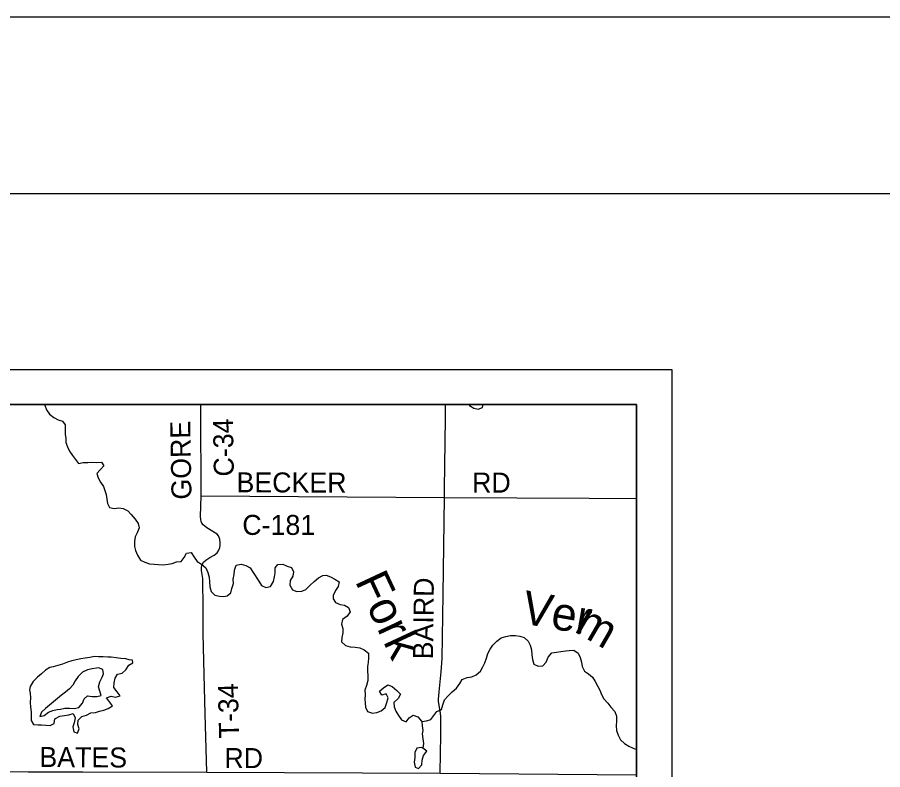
# Model space of a CAD drawing. Extents: x 0 to 34, y 0 to 22.
# Drawn here: x 7.141 to 9.599, y 19.863 to 22 of the extents above; entities that cross this region are included whole.
import ezdxf

# ---------------------------------------------------------------- set-up
doc = ezdxf.new("R2010")
doc.units = 0
for name, color, linetype in [('GM_X_Corporation', 7, 'Continuous'), ('GM_X_County_Road', 7, 'Continuous'), ('GM_X_County_Road_Text', 7, 'Continuous'), ('GM_X_Minor_Lake', 7, 'Continuous'), ('GM_X_Minor_River', 7, 'Continuous'), ('GM_X_Minor_River_Text', 7, 'Continuous'), ('GM_X_Township_Road', 7, 'Continuous'), ('GM_X_Township_Road_Text', 7, 'Continuous'), ('SH_Border', 7, 'Continuous'), ('SH_Cut_Line', 7, 'Continuous'), ('SH_Data', 7, 'Continuous')]:
    doc.layers.add(name, color=color, linetype=linetype)

msp = doc.modelspace()

# ---------------------------------------------------------------- linework, layer by layer
at = {"layer": 'GM_X_Corporation'}
msp.add_lwpolyline([(8.9, 14.1), (8.9, 20.9), (6.9799, 20.9), (6.9799, 20.8943), (6.9814, 20.8368), (6.9837, 20.7502), (6.9864, 20.657), (6.9927, 20.4427), (6.9931, 20.4255), (6.9989, 19.9212), (7.0018, 19.871), (7.0046, 19.8599), (7.0077, 19.6756), (7.0107, 19.4664), (7.0305, 18.5559), (7.0429, 18.0629), (7.0494, 17.8247), (7.0577, 17.449), (7.0649, 17.2134), (7.0651, 17.204), (7.0717, 16.9849), (7.0838, 16.6084), (7.1072, 15.3824)], dxfattribs=at)
msp.add_lwpolyline([(8.9, 19.8484), (8.9, 20.9), (6.9799, 20.9), (6.9799, 20.8943), (6.9814, 20.8368), (6.9837, 20.7502), (6.9864, 20.657), (6.9927, 20.4427), (6.9931, 20.4255), (6.9989, 19.9212), (7.0018, 19.871), (7.0046, 19.8599), (7.1717, 19.8568), (7.3272, 19.8568), (7.6795, 19.8561), (8.3424, 19.8533)], close=True, dxfattribs=at)
at = {"layer": 'GM_X_County_Road'}
for points in [[(7.663, 20.6406), (7.6626, 20.8828), (7.6622, 20.9)], [(7.663, 20.6406), (8.3545, 20.636), (8.7653, 20.634), (8.9, 20.6328)]]:
    msp.add_lwpolyline(points, dxfattribs=at)
at = {"layer": 'GM_X_Minor_Lake'}
for points in [[(7.4688, 20.1739), (7.459, 20.1752), (7.4491, 20.1774), (7.4354, 20.1792), (7.4217, 20.1805), (7.408, 20.1823), (7.3985, 20.1825), (7.3855, 20.1835), (7.3722, 20.1837), (7.3604, 20.184), (7.3475, 20.1819), (7.3342, 20.1799), (7.3213, 20.1778), (7.3084, 20.175), (7.2963, 20.1722), (7.2834, 20.1679), (7.2694, 20.1628), (7.2568, 20.1592), (7.2436, 20.1553), (7.2341, 20.1533), (7.2216, 20.1459), (7.2096, 20.1351), (7.1983, 20.1255), (7.1859, 20.1132), (7.178, 20.0994), (7.1755, 20.0895), (7.1775, 20.08), (7.1784, 20.0671), (7.1782, 20.0538), (7.1791, 20.0409), (7.1804, 20.0276), (7.1809, 20.0155), (7.1806, 20.0025), (7.1872, 19.9912)], [(7.1872, 19.9912), (7.2002, 19.9906), (7.2097, 19.9903), (7.2226, 19.9893), (7.2344, 19.9887), (7.2462, 19.9942), (7.2483, 20.0071), (7.2619, 20.0153), (7.2756, 20.0166), (7.2881, 20.019), (7.3002, 20.0225), (7.3061, 20.0101), (7.3028, 19.9964), (7.2988, 19.9845), (7.3016, 19.9709), (7.3127, 19.9664), (7.3167, 19.979), (7.3131, 19.9911), (7.3145, 20.0037), (7.3247, 20.0137), (7.3379, 20.018), (7.35, 20.0246), (7.3637, 20.0256), (7.3751, 20.0287), (7.3872, 20.0319), (7.3997, 20.037), (7.4114, 20.044), (7.4033, 20.0557), (7.3944, 20.067), (7.4077, 20.072), (7.4203, 20.0692), (7.4332, 20.0727), (7.4251, 20.0844), (7.4154, 20.0965), (7.4168, 20.1094), (7.4193, 20.1231), (7.4256, 20.1346), (7.4389, 20.1374), (7.4498, 20.147), (7.4577, 20.16), (7.4698, 20.1666), (7.4688, 20.1739)], [(7.2548, 20.0338), (7.2636, 20.035), (7.2765, 20.0375), (7.2894, 20.038), (7.3031, 20.0363), (7.3156, 20.0394), (7.3261, 20.0521), (7.331, 20.0639), (7.3407, 20.0728), (7.3537, 20.0707), (7.3674, 20.0708), (7.3799, 20.0736), (7.3756, 20.0861), (7.372, 20.0986), (7.3761, 20.1123), (7.3827, 20.1261), (7.3857, 20.1356), (7.384, 20.1478), (7.3722, 20.1522), (7.3664, 20.1513)], [(7.2548, 20.0338), (7.2636, 20.035), (7.2765, 20.0375), (7.2894, 20.038), (7.3031, 20.0363), (7.3156, 20.0394), (7.3261, 20.0521), (7.331, 20.0639), (7.3407, 20.0728), (7.3537, 20.0707), (7.3674, 20.0708), (7.3799, 20.0736), (7.3756, 20.0861), (7.372, 20.0986), (7.3761, 20.1123), (7.3827, 20.1261), (7.3857, 20.1356), (7.384, 20.1478), (7.3722, 20.1522), (7.3663, 20.1513)], [(7.3664, 20.1513), (7.3665, 20.1514), (7.3536, 20.1493), (7.3403, 20.1465), (7.3267, 20.1395), (7.3146, 20.128), (7.3056, 20.1157), (7.2986, 20.1031), (7.2899, 20.0927), (7.2782, 20.0827), (7.2669, 20.0742), (7.2552, 20.0653), (7.2443, 20.0561), (7.2326, 20.0461), (7.2213, 20.0368), (7.21, 20.0264), (7.2052, 20.0138), (7.2178, 20.017), (7.2302, 20.0267), (7.2419, 20.0314), (7.2548, 20.0338)], [(7.3664, 20.1513), (7.3536, 20.1493), (7.3403, 20.1465), (7.3267, 20.1395), (7.3146, 20.128), (7.3056, 20.1157), (7.2986, 20.1031), (7.2899, 20.0927), (7.2782, 20.0827), (7.2669, 20.0742), (7.2552, 20.0653), (7.2443, 20.0561), (7.2326, 20.0461), (7.2213, 20.0368), (7.21, 20.0264), (7.2052, 20.0138), (7.2178, 20.017), (7.2302, 20.0267), (7.2419, 20.0314), (7.2548, 20.0338)], [(8.2934, 19.9242), (8.2896, 19.926), (8.2759, 19.9244), (8.27, 19.9118), (8.2701, 19.8977), (8.2688, 19.884), (8.2708, 19.8703), (8.2808, 19.8659)], [(8.2933, 19.9243), (8.2896, 19.926), (8.2759, 19.9244), (8.27, 19.9118), (8.2701, 19.8977), (8.2688, 19.884), (8.2708, 19.8703), (8.2808, 19.8659)], [(8.2808, 19.8659), (8.2901, 19.8763), (8.2907, 19.89), (8.2952, 19.9029), (8.3045, 19.9156), (8.2934, 19.9242)], [(8.2808, 19.8659), (8.2901, 19.8763), (8.2907, 19.89), (8.2952, 19.9029), (8.3045, 19.9156), (8.2934, 19.9242)]]:
    msp.add_lwpolyline(points, dxfattribs=at)
at = {"layer": 'GM_X_Minor_River'}
for points in [[(7.2188, 20.9), (7.2196, 20.8983), (7.2246, 20.8851), (7.2324, 20.8726), (7.2451, 20.8636), (7.2573, 20.8569), (7.2699, 20.8525), (7.2769, 20.842), (7.2772, 20.8146), (7.2792, 20.8048), (7.2793, 20.7918), (7.284, 20.7797), (7.2899, 20.7676), (7.2984, 20.7556), (7.3154, 20.7322), (7.3287, 20.735), (7.3412, 20.7359), (7.3541, 20.7361), (7.3671, 20.7358), (7.3808, 20.7364), (7.387, 20.7262), (7.3768, 20.7151), (7.3674, 20.7043), (7.3706, 20.6918), (7.378, 20.6794), (7.3865, 20.6673), (7.3901, 20.6555), (7.3936, 20.6442), (7.3957, 20.6313), (7.3973, 20.6188), (7.4032, 20.6074), (7.4161, 20.6049), (7.4298, 20.6066), (7.4424, 20.6045), (7.455, 20.5978), (7.465, 20.5876), (7.4758, 20.5741), (7.4843, 20.562), (7.4875, 20.5495), (7.4816, 20.5358), (7.476, 20.5239), (7.4739, 20.511), (7.4744, 20.4973), (7.4772, 20.4852), (7.4827, 20.4719), (7.4912, 20.4583), (7.5034, 20.4528), (7.5168, 20.4476), (7.5297, 20.4463), (7.5427, 20.446), (7.5556, 20.4447), (7.5693, 20.4463), (7.5811, 20.4484), (7.5936, 20.4531), (7.6069, 20.4547), (7.6151, 20.4659), (7.6214, 20.4777), (7.6347, 20.4798), (7.6436, 20.4662), (7.6521, 20.4541), (7.664, 20.4463), (7.6763, 20.4358), (7.6826, 20.4229), (7.6865, 20.4101), (7.6867, 20.3964), (7.688, 20.3827), (7.6915, 20.3691), (7.7027, 20.3589), (7.7156, 20.3557), (7.7274, 20.3551), (7.7369, 20.3567), (7.7475, 20.3655), (7.7504, 20.3777), (7.7548, 20.3915), (7.7543, 20.404), (7.7568, 20.417), (7.7582, 20.4299), (7.763, 20.4436), (7.7766, 20.4464)], [(8.4244, 20.9), (8.4258, 20.8978), (8.4377, 20.8896), (8.4499, 20.887), (8.4627, 20.8918), (8.4642, 20.9)], [(7.7766, 20.4464), (7.79, 20.4428), (7.8026, 20.4361), (7.8111, 20.4229), (7.8274, 20.398), (7.8351, 20.3863), (7.8474, 20.3808), (7.8599, 20.3836), (7.8692, 20.397), (7.8714, 20.4103), (7.8735, 20.4225), (7.8734, 20.4362), (7.8816, 20.4458), (7.8953, 20.4471), (7.9072, 20.4411), (7.9197, 20.4375), (7.926, 20.425), (7.9242, 20.4128), (7.916, 20.4002), (7.915, 20.3872), (7.9227, 20.374), (7.9354, 20.3689), (7.949, 20.3702), (7.9608, 20.3752), (7.9724, 20.3864), (7.9845, 20.3975), (7.9962, 20.4079), (8.0086, 20.4145), (8.0185, 20.415), (8.0311, 20.411), (8.043, 20.4043), (8.0549, 20.3965), (8.0527, 20.3835), (8.0445, 20.3716), (8.0382, 20.3579), (8.0379, 20.3484), (8.0453, 20.3374), (8.0579, 20.3319), (8.0701, 20.3305), (8.0823, 20.3234), (8.087, 20.3113), (8.0777, 20.2994), (8.0648, 20.2894), (8.0623, 20.2765), (8.0659, 20.2643), (8.066, 20.2514), (8.0627, 20.2388), (8.0621, 20.2259), (8.0737, 20.2158), (8.087, 20.2121), (8.1007, 20.2108), (8.1137, 20.2086), (8.1263, 20.2038), (8.1382, 20.1937), (8.1383, 20.1808), (8.1377, 20.1671), (8.136, 20.1557), (8.1361, 20.1435), (8.137, 20.1299), (8.1368, 20.1162), (8.1328, 20.1025), (8.1283, 20.0891), (8.1289, 20.0762), (8.1279, 20.0625), (8.1295, 20.053), (8.1304, 20.0401), (8.1355, 20.0284), (8.1496, 20.0236), (8.1625, 20.0257), (8.1747, 20.0304), (8.186, 20.04), (8.1911, 20.0537), (8.1948, 20.0667), (8.1886, 20.0788), (8.1761, 20.0748), (8.1698, 20.0858), (8.1811, 20.0954), (8.194, 20.1043), (8.2058, 20.0991), (8.2189, 20.0879), (8.2293, 20.0777), (8.223, 20.0647), (8.2109, 20.054), (8.2118, 20.041), (8.2165, 20.0293), (8.2239, 20.0169), (8.2328, 20.0048), (8.2454, 19.9993), (8.2544, 20.01), (8.2657, 20.0177), (8.2791, 20.0133), (8.2895, 20.0009)], [(8.2895, 20.0009), (8.2903, 19.9998), (8.3036, 20.0018), (8.3157, 20.0058), (8.3243, 20.0173), (8.3329, 20.028), (8.3458, 20.0339), (8.3495, 20.0472), (8.3546, 20.0609), (8.3648, 20.0725), (8.3764, 20.0844), (8.3889, 20.0944), (8.3978, 20.1074), (8.4049, 20.1193), (8.4186, 20.1248), (8.4322, 20.1268), (8.4447, 20.1319), (8.4564, 20.1423), (8.4631, 20.1549), (8.4694, 20.1668), (8.4739, 20.1797), (8.4779, 20.1931), (8.4842, 20.2053), (8.4921, 20.2168), (8.503, 20.228), (8.5154, 20.2376), (8.5283, 20.2416), (8.542, 20.2444), (8.5557, 20.2445), (8.5683, 20.242), (8.5809, 20.238), (8.592, 20.2282), (8.5978, 20.2165), (8.6018, 20.2029), (8.6027, 20.1892), (8.604, 20.1755), (8.608, 20.1627), (8.6206, 20.1571), (8.6335, 20.1576), (8.6433, 20.1688), (8.6492, 20.1821), (8.6589, 20.1944), (8.6722, 20.1972), (8.6851, 20.1989), (8.6988, 20.2002), (8.7083, 20.2018), (8.722, 20.2024), (8.7339, 20.1938), (8.7397, 20.1813), (8.7437, 20.1684), (8.7454, 20.1559), (8.7516, 20.1423), (8.7631, 20.1356), (8.7746, 20.1254), (8.782, 20.1138), (8.7893, 20.1009), (8.7952, 20.0892), (8.7999, 20.0767), (8.8073, 20.0639), (8.8181, 20.0515), (8.8273, 20.0402), (8.8381, 20.0281), (8.8432, 20.0145), (8.8426, 20.0008), (8.8424, 19.9879), (8.8429, 19.9742), (8.8472, 19.9614), (8.8546, 19.9478), (8.8654, 19.9369), (8.8776, 19.9298), (8.8902, 19.9239), (8.9, 19.9199)], [(8.2903, 19.9999), (8.2904, 19.9991), (8.2915, 19.9876), (8.2925, 19.974), (8.2914, 19.9644), (8.2931, 19.9508), (8.2944, 19.9371), (8.2934, 19.9242)]]:
    msp.add_lwpolyline(points, dxfattribs=at)
at = {"layer": 'GM_X_Township_Road'}
for points in [[(8.3545, 20.636), (8.3545, 20.6618), (8.3569, 20.8598), (8.3576, 20.9)], [(7.6797, 19.8556), (7.6745, 20.0219), (7.6723, 20.1332), (7.6694, 20.2497), (7.6688, 20.3296), (7.6685, 20.3953), (7.6681, 20.4063), (7.6665, 20.417), (7.6646, 20.4285), (7.6648, 20.4384), (7.6661, 20.4462), (7.6701, 20.4526), (7.6763, 20.4583), (7.688, 20.4652), (7.7008, 20.4725), (7.709, 20.4789), (7.7134, 20.4862), (7.7161, 20.4939), (7.7172, 20.5004), (7.7172, 20.5072), (7.7161, 20.5174), (7.713, 20.5269), (7.7086, 20.5322), (7.6794, 20.5503), (7.6743, 20.5548), (7.6692, 20.5583), (7.6657, 20.5636), (7.6637, 20.5683), (7.6626, 20.574), (7.6619, 20.5824), (7.663, 20.6406)], [(8.3426, 19.8527), (8.3432, 19.91), (8.3441, 19.9593), (8.3443, 19.9836), (8.3443, 20.002), (8.3436, 20.0142), (8.3428, 20.0221), (8.3417, 20.0292), (8.3372, 20.0564), (8.3372, 20.0637), (8.3397, 20.0845), (8.3454, 20.1413), (8.3474, 20.1785), (8.3505, 20.3601), (8.3545, 20.636)]]:
    msp.add_lwpolyline(points, dxfattribs=at)
at = {"layer": 'SH_Border'}
msp.add_lwpolyline([(1.5, 21.5), (33.5, 21.5), (33.5, 0.5), (1.5, 0.5)], close=True, dxfattribs=at)
at = {"layer": 'SH_Cut_Line'}
msp.add_lwpolyline([(0, 0), (34, 0), (34, 22), (0, 22)], close=True, dxfattribs=at)
at = {"layer": 'SH_Data'}
for p, q in [((2, 21), (9, 21)), ((9, 21), (9, 14)), ((2.1, 20.9), (8.9, 20.9)), ((8.9, 20.9), (8.9, 14.1))]:
    msp.add_line(p, q, dxfattribs=at)

# ---------------------------------------------------------------- texts
at = {"layer": 'GM_X_County_Road_Text'}
for s, rotation, p in [('GORE', 91.0099, (7.6362, 20.6306)), ('C-34', 91.0299, (7.7565, 20.6961)), ('BECKER', 359.8259, (7.7637, 20.6508)), ('RD', 0, (8.4328, 20.65)), ('C-181', 0, (7.7803, 20.5298)), ('BATES', 359.5662, (7.2038, 19.8708)), ('RD', 0, (7.7294, 19.8675))]:
    msp.add_text(s, height=0.05682, rotation=rotation, dxfattribs=at).set_placement(p)
at = {"layer": 'GM_X_Minor_River_Text'}
for s, height, rotation, p in [('Fork', 0.09475, 294.9949, (8.0993, 20.399)), ('Ver', 0.09475, 349.9953, (8.5697, 20.2793)), ('m', 0.0948, 329.9947, (8.7196, 20.2565))]:
    msp.add_text(s, height=height, rotation=rotation, dxfattribs=at).set_placement(p)
at = {"layer": 'GM_X_Township_Road_Text'}
for s, rotation, p in [('BAIRD', 89.3359, (8.3219, 20.1762)), ('T-34', 91.4137, (7.7713, 19.9526))]:
    msp.add_text(s, height=0.05682, rotation=rotation, dxfattribs=at).set_placement(p)

doc.saveas('drawing.dxf')
